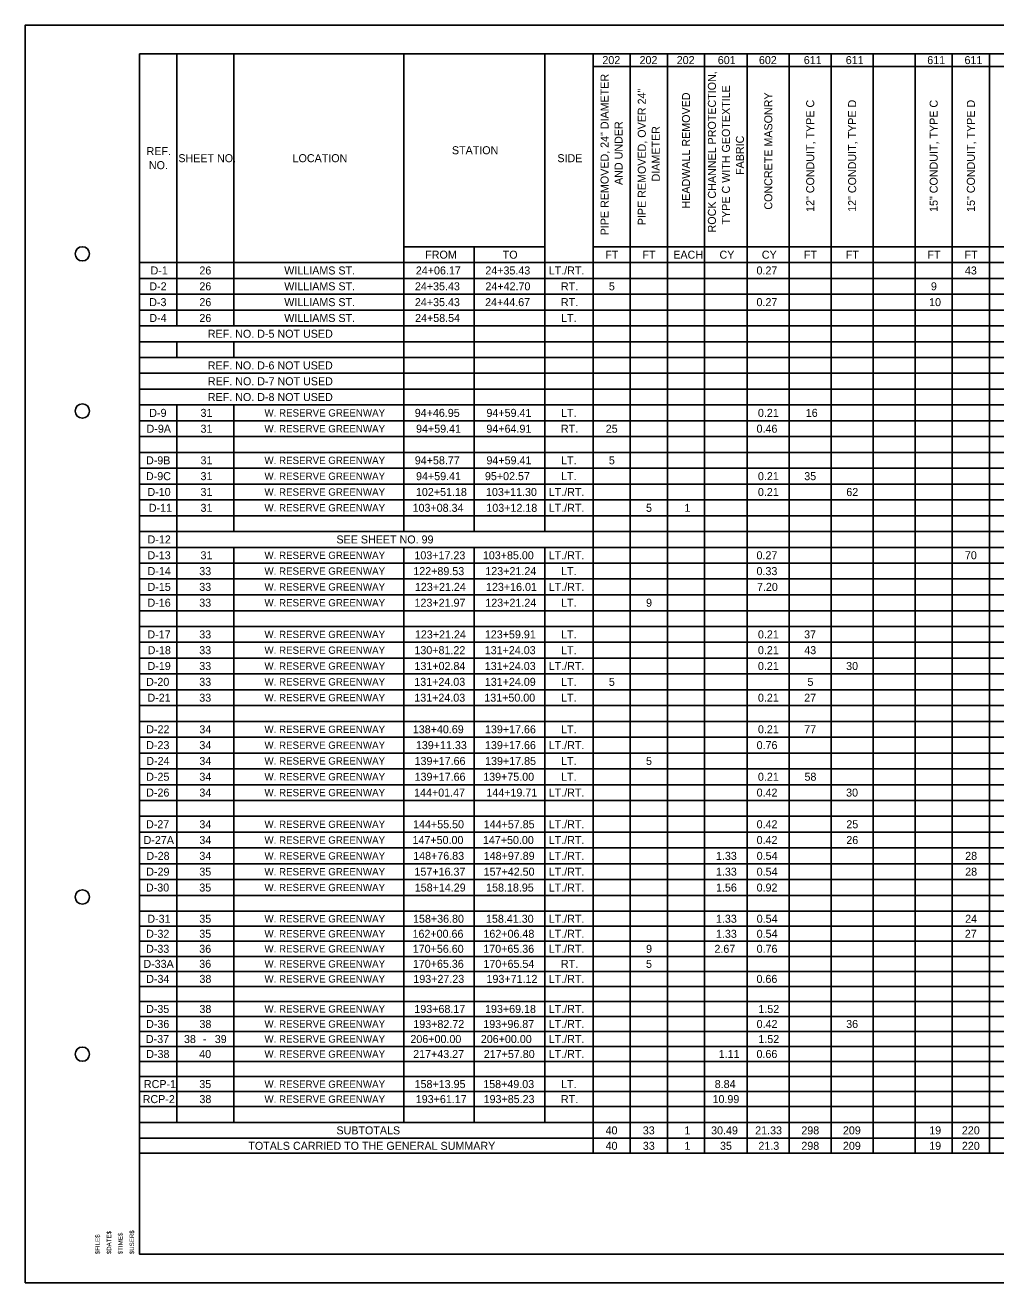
# Model space of a CAD drawing. Extents: x -16 to 102, y -13 to 9.
# Drawn here: x -16.37 to 0.6, y -12.91 to 9.09 of the extents above; entities that cross this region are included whole.
import ezdxf

# ---------------------------------------------------------------- set-up
doc = ezdxf.new("R2010")
doc.units = 0
for name, color, linetype in [('PV_P_EOP', 7, 'Continuous'), ('SH_Border', 7, 'Continuous'), ('SH_Cut_Line', 7, 'Continuous'), ('TX_P_1', 7, 'Continuous'), ('TX_P_Misc', 7, 'Continuous')]:
    doc.layers.add(name, color=color, linetype=linetype)

msp = doc.modelspace()

# ---------------------------------------------------------------- linework, layer by layer
at = {"layer": 'SH_Border'}
msp.add_lwpolyline([(-14.371, 8.593), (17.129, 8.593), (17.129, -12.407), (-14.371, -12.407)], close=True, dxfattribs=at)
for centre in [(-15.371, 5.093), (-15.371, 2.343), (-15.371, -6.157), (-15.371, -8.907)]:
    msp.add_circle(centre, 0.125, dxfattribs=at)
at = {"layer": 'SH_Cut_Line'}
msp.add_lwpolyline([(-16.371, -12.907), (17.629, -12.907), (17.629, 9.093), (-16.371, 9.093)], close=True, dxfattribs=at)
at = {"layer": 'TX_P_1'}
for p, q in [((-14.371, 8.593), (10.564, 8.593)), ((-14.371, 8.593), (-14.371, -10.641)), ((-13.721, 8.593), (-13.721, 3.833)), ((-12.725, 8.593), (-12.725, 3.833)), ((-9.75, 8.593), (-9.75, 0.235)), ((-7.286, 8.593), (-7.286, 0.235)), ((-6.442, 8.593), (-6.442, -10.641)), ((-5.792, 8.593), (-5.792, -10.641)), ((-5.142, 8.593), (-5.142, -10.641)), ((-4.491, 8.593), (-4.491, -10.641)), ((-3.744, 8.593), (-3.744, -10.641)), ((-3.011, 8.593), (-3.011, -10.641)), ((-2.277, 8.593), (-2.277, -10.641)), ((-1.544, 8.593), (-1.544, -10.641)), ((-0.811, 8.593), (-0.811, -10.641)), ((-0.16, 8.593), (-0.16, -10.641)), ((0.49, 8.593), (0.49, -10.641)), ((-6.442, 8.372), (10.564, 8.372)), ((-9.75, 5.217), (-7.286, 5.217)), ((-8.518, 5.217), (-8.518, 0.235)), ((-6.442, 5.217), (10.564, 5.217)), ((-14.371, 4.94), (10.564, 4.94)), ((-14.371, 4.663), (10.564, 4.663)), ((-14.371, 4.386), (10.564, 4.386)), ((-14.371, 4.11), (10.564, 4.11)), ((-14.371, 3.833), (10.564, 3.833)), ((-14.371, 3.556), (10.564, 3.556)), ((-13.721, 3.556), (-13.721, 3.279)), ((-12.725, 3.556), (-12.725, 3.279)), ((-14.371, 3.279), (10.564, 3.279)), ((-14.371, 3.003), (10.564, 3.003)), ((-14.371, 2.726), (10.564, 2.726)), ((-14.371, 2.449), (10.564, 2.449)), ((-13.721, 2.449), (-13.721, -10.101)), ((-12.725, 2.449), (-12.725, 0.235)), ((-14.371, 2.172), (10.564, 2.172)), ((-14.371, 1.896), (10.564, 1.896)), ((-14.371, 1.619), (10.564, 1.619)), ((-14.371, 1.342), (10.564, 1.342)), ((-14.371, 1.065), (10.564, 1.065)), ((-14.371, 0.789), (10.564, 0.789)), ((-14.371, 0.512), (10.564, 0.512)), ((-14.371, 0.235), (10.564, 0.235)), ((-14.371, -0.042), (10.564, -0.042)), ((-12.725, -0.042), (-12.725, -10.101)), ((-9.75, -0.042), (-9.75, -10.101)), ((-8.518, -0.042), (-8.518, -10.101)), ((-7.286, -0.042), (-7.286, -10.101)), ((-14.371, -0.318), (10.564, -0.318)), ((-14.371, -0.595), (10.564, -0.595)), ((-14.371, -0.872), (10.564, -0.872)), ((-14.371, -1.149), (10.564, -1.149)), ((-14.371, -1.425), (10.564, -1.425)), ((-14.371, -1.702), (10.564, -1.702)), ((-14.371, -1.979), (10.564, -1.979)), ((-14.371, -2.256), (10.564, -2.256)), ((-14.371, -2.532), (10.564, -2.532)), ((-14.371, -2.809), (10.564, -2.809)), ((-14.371, -3.086), (10.564, -3.086)), ((-14.371, -3.363), (10.564, -3.363)), ((-14.371, -3.639), (10.564, -3.639)), ((-14.371, -3.916), (10.564, -3.916)), ((-14.371, -4.193), (10.564, -4.193)), ((-14.371, -4.47), (10.564, -4.47)), ((-14.371, -4.746), (10.564, -4.746)), ((-14.371, -5.023), (10.564, -5.023)), ((-14.371, -5.3), (10.564, -5.3)), ((-14.371, -5.577), (10.564, -5.577)), ((-14.371, -5.853), (10.564, -5.853)), ((-14.371, -6.13), (10.564, -6.13)), ((-14.371, -6.407), (10.564, -6.407)), ((-14.371, -6.67), (10.564, -6.67)), ((-14.371, -6.933), (10.564, -6.933)), ((-14.371, -7.196), (10.564, -7.196)), ((-14.371, -7.458), (10.564, -7.458)), ((-14.371, -7.721), (10.564, -7.721)), ((-14.371, -7.984), (10.564, -7.984)), ((-14.371, -8.247), (10.564, -8.247)), ((-14.371, -8.51), (10.564, -8.51)), ((-14.371, -8.773), (10.564, -8.773)), ((-14.371, -9.036), (10.564, -9.036)), ((-14.371, -9.299), (10.564, -9.299)), ((-14.371, -9.562), (10.564, -9.562)), ((-14.371, -9.825), (10.564, -9.825)), ((-14.371, -10.101), (10.564, -10.101)), ((-14.371, -10.378), (10.564, -10.378)), ((-14.371, -10.641), (10.564, -10.641))]:
    msp.add_line(p, q, dxfattribs=at)

# ---------------------------------------------------------------- texts
at = {"layer": 'PV_P_EOP'}
for s, height, p in [('REF.', 0.14, (-14.248, 6.819)), ('SHEET NO.', 0.14, (-13.693, 6.696)), ('LOCATION', 0.14, (-11.695, 6.696)), ('STATION', 0.14, (-8.909, 6.835)), ('SIDE', 0.14, (-7.065, 6.696)), ('NO.', 0.14, (-14.208, 6.574)), ('FROM', 0.14, (-9.376, 5.008)), ('TO', 0.14, (-8.021, 5.008)), ('SUBTOTALS', 0.14, (-10.928, -10.31)), ('TOTALS CARRIED TO THE GENERAL SUMMARY', 0.14004, (-12.469, -10.58))]:
    msp.add_text(s, height=height, dxfattribs=at).set_placement(p)
at = {"layer": 'TX_P_1'}
for s, height, p in [('202', 0.14, (-6.278, 8.412)), ('202', 0.14, (-5.628, 8.412)), ('202', 0.14, (-4.978, 8.412)), ('601', 0.14, (-4.26, 8.412)), ('602', 0.14, (-3.541, 8.412)), ('611', 0.14, (-2.756, 8.412)), ('611', 0.14, (-2.022, 8.412)), ('611', 0.14, (-0.597, 8.412)), ('611', 0.14, (0.054, 8.412)), ('FT', 0.14, (-6.227, 5.008)), ('FT', 0.14, (-5.577, 5.008)), ('EACH', 0.14, (-5.038, 5.008)), ('CY', 0.14, (-4.23, 5.008)), ('CY', 0.14, (-3.49, 5.008)), ('FT', 0.14, (-2.754, 5.008)), ('FT', 0.14, (-2.021, 5.008)), ('FT', 0.14, (-0.595, 5.008)), ('FT', 0.14, (0.055, 5.008)), ('D-1', 0.14, (-14.179, 4.732)), ('26', 0.14, (-13.325, 4.732)), ('WILLIAMS ST.', 0.14004, (-11.841, 4.732)), ('24+06.17', 0.14, (-9.54, 4.732)), ('24+35.43', 0.14, (-8.325, 4.732)), ('LT./RT.', 0.14, (-7.216, 4.732)), ('0.27', 0.14, (-3.583, 4.732)), ('43', 0.14, (0.061, 4.732)), ('D-2', 0.14, (-14.2, 4.455)), ('26', 0.14, (-13.325, 4.455)), ('WILLIAMS ST.', 0.14004, (-11.841, 4.455)), ('24+35.43', 0.14, (-9.556, 4.455)), ('24+42.70', 0.14, (-8.323, 4.455)), ('RT.', 0.14, (-7.003, 4.455)), ('5', 0.14, (-6.165, 4.455)), ('9', 0.14, (-0.533, 4.455)), ('D-3', 0.14, (-14.202, 4.178)), ('26', 0.14, (-13.325, 4.178)), ('WILLIAMS ST.', 0.14004, (-11.841, 4.178)), ('24+35.43', 0.14, (-9.556, 4.178)), ('24+44.67', 0.14, (-8.328, 4.178)), ('RT.', 0.14, (-7.003, 4.178)), ('0.27', 0.14, (-3.583, 4.178)), ('10', 0.14, (-0.565, 4.178)), ('D-4', 0.14, (-14.2, 3.901)), ('26', 0.14, (-13.325, 3.901)), ('WILLIAMS ST.', 0.14004, (-11.841, 3.901)), ('24+58.54', 0.14, (-9.553, 3.901)), ('LT.', 0.14, (-7, 3.901)), ('REF. NO. D-5 NOT USED', 0.14004, (-13.177, 3.625)), ('REF. NO. D-6 NOT USED', 0.14004, (-13.178, 3.071)), ('REF. NO. D-7 NOT USED', 0.14004, (-13.176, 2.794)), ('REF. NO. D-8 NOT USED', 0.14004, (-13.177, 2.518)), ('D-9', 0.14, (-14.201, 2.241)), ('31', 0.14, (-13.305, 2.241)), ('W. RESERVE GREENWAY', 0.12731, (-12.187, 2.247)), ('94+46.95', 0.14, (-9.559, 2.241)), ('94+59.41', 0.14, (-8.305, 2.241)), ('LT.', 0.14, (-7, 2.241)), ('0.21', 0.14, (-3.558, 2.241)), ('16', 0.14, (-2.722, 2.241)), ('D-9A', 0.14, (-14.248, 1.964)), ('31', 0.14, (-13.305, 1.964)), ('W. RESERVE GREENWAY', 0.12731, (-12.187, 1.97)), ('94+59.41', 0.14, (-9.536, 1.964)), ('94+64.91', 0.14, (-8.306, 1.964)), ('RT.', 0.14, (-7.003, 1.964)), ('25', 0.14, (-6.219, 1.964)), ('0.46', 0.14, (-3.582, 1.964)), ('D-9B', 0.14, (-14.258, 1.411)), ('31', 0.14, (-13.305, 1.411)), ('W. RESERVE GREENWAY', 0.12731, (-12.187, 1.417)), ('94+58.77', 0.14, (-9.558, 1.411)), ('94+59.41', 0.14, (-8.305, 1.411)), ('LT.', 0.14, (-7, 1.411)), ('5', 0.14, (-6.165, 1.411)), ('D-9C', 0.14, (-14.259, 1.134)), ('31', 0.14, (-13.305, 1.134)), ('W. RESERVE GREENWAY', 0.12731, (-12.187, 1.14)), ('94+59.41', 0.14, (-9.536, 1.134)), ('95+02.57', 0.14, (-8.332, 1.134)), ('LT.', 0.14, (-7, 1.134)), ('0.21', 0.14, (-3.558, 1.134)), ('35', 0.14, (-2.748, 1.134)), ('D-10', 0.14, (-14.233, 0.857)), ('31', 0.14, (-13.305, 0.857)), ('W. RESERVE GREENWAY', 0.12731, (-12.187, 0.863)), ('102+51.18', 0.14, (-9.538, 0.857)), ('103+11.30', 0.14, (-8.313, 0.857)), ('LT./RT.', 0.14, (-7.216, 0.857)), ('0.21', 0.14, (-3.558, 0.857)), ('62', 0.14, (-2.013, 0.857)), ('D-11', 0.14, (-14.209, 0.58)), ('31', 0.14, (-13.305, 0.58)), ('W. RESERVE GREENWAY', 0.12731, (-12.187, 0.587)), ('103+08.34', 0.14, (-9.597, 0.58)), ('103+12.18', 0.14, (-8.307, 0.58)), ('LT./RT.', 0.14, (-7.216, 0.58)), ('5', 0.14, (-5.515, 0.58)), ('1', 0.14, (-4.843, 0.58)), ('D-12', 0.14, (-14.23, 0.027)), ('SEE SHEET NO. 99', 0.14004, (-10.928, 0.027)), ('D-13', 0.14, (-14.232, -0.25)), ('31', 0.14, (-13.305, -0.25)), ('W. RESERVE GREENWAY', 0.12731, (-12.187, -0.244)), ('103+17.23', 0.14, (-9.565, -0.25)), ('103+85.00', 0.14, (-8.368, -0.25)), ('LT./RT.', 0.14, (-7.216, -0.25)), ('0.27', 0.14, (-3.583, -0.25)), ('70', 0.14, (0.061, -0.25)), ('D-14', 0.14, (-14.23, -0.527)), ('33', 0.14, (-13.327, -0.527)), ('W. RESERVE GREENWAY', 0.12731, (-12.187, -0.52)), ('122+89.53', 0.14, (-9.584, -0.527)), ('123+21.24', 0.14, (-8.325, -0.527)), ('LT.', 0.14, (-7, -0.527)), ('0.33', 0.14, (-3.583, -0.527)), ('LT./RT.', 0.14, (-7.216, -0.803)), ('D-15', 0.14, (-14.231, -0.803)), ('33', 0.14, (-13.327, -0.803)), ('W. RESERVE GREENWAY', 0.12731, (-12.187, -0.797)), ('123+21.24', 0.14, (-9.556, -0.803)), ('123+16.01', 0.14, (-8.313, -0.803)), ('7.20', 0.14, (-3.575, -0.803)), ('D-16', 0.14, (-14.232, -1.08)), ('33', 0.14, (-13.327, -1.08)), ('W. RESERVE GREENWAY', 0.12731, (-12.187, -1.074)), ('123+21.97', 0.14, (-9.563, -1.08)), ('123+21.24', 0.14, (-8.325, -1.08)), ('LT.', 0.14, (-7, -1.08)), ('9', 0.14, (-5.514, -1.08)), ('D-17', 0.14, (-14.234, -1.634)), ('33', 0.14, (-13.327, -1.634)), ('W. RESERVE GREENWAY', 0.12731, (-12.187, -1.627)), ('123+21.24', 0.14, (-9.556, -1.634)), ('123+59.91', 0.14, (-8.333, -1.634)), ('LT.', 0.14, (-7, -1.634)), ('0.21', 0.14, (-3.558, -1.634)), ('37', 0.14, (-2.751, -1.634)), ('D-18', 0.14, (-14.229, -1.91)), ('33', 0.14, (-13.327, -1.91)), ('W. RESERVE GREENWAY', 0.12731, (-12.187, -1.904)), ('130+81.22', 0.14, (-9.565, -1.91)), ('131+24.03', 0.14, (-8.335, -1.91)), ('LT.', 0.14, (-7, -1.91)), ('0.21', 0.14, (-3.558, -1.91)), ('43', 0.14, (-2.748, -1.91)), ('D-19', 0.14, (-14.231, -2.187)), ('33', 0.14, (-13.327, -2.187)), ('W. RESERVE GREENWAY', 0.12731, (-12.187, -2.181)), ('131+02.84', 0.14, (-9.564, -2.187)), ('131+24.03', 0.14, (-8.335, -2.187)), ('LT./RT.', 0.14, (-7.216, -2.187)), ('0.21', 0.14, (-3.558, -2.187)), ('30', 0.14, (-2.016, -2.187)), ('D-20', 0.14, (-14.257, -2.464)), ('33', 0.14, (-13.327, -2.464)), ('W. RESERVE GREENWAY', 0.12731, (-12.187, -2.458)), ('131+24.03', 0.14, (-9.567, -2.464)), ('131+24.09', 0.14, (-8.334, -2.464)), ('LT.', 0.14, (-7, -2.464)), ('5', 0.14, (-6.165, -2.464)), ('5', 0.14, (-2.692, -2.464)), ('D-21', 0.14, (-14.233, -2.741)), ('33', 0.14, (-13.327, -2.741)), ('W. RESERVE GREENWAY', 0.12731, (-12.187, -2.734)), ('131+24.03', 0.14, (-9.567, -2.741)), ('131+50.00', 0.14, (-8.343, -2.741)), ('LT.', 0.14, (-7, -2.741)), ('0.21', 0.14, (-3.558, -2.741)), ('27', 0.14, (-2.749, -2.741)), ('D-22', 0.14, (-14.254, -3.294)), ('34', 0.14, (-13.325, -3.294)), ('W. RESERVE GREENWAY', 0.12731, (-12.187, -3.288)), ('138+40.69', 0.14, (-9.593, -3.294)), ('139+17.66', 0.14, (-8.331, -3.294)), ('LT.', 0.14, (-7, -3.294)), ('0.21', 0.14, (-3.558, -3.294)), ('77', 0.14, (-2.749, -3.294)), ('D-23', 0.14, (-14.255, -3.571)), ('34', 0.14, (-13.325, -3.571)), ('W. RESERVE GREENWAY', 0.12731, (-12.187, -3.565)), ('139+11.33', 0.14, (-9.539, -3.571)), ('139+17.66', 0.14, (-8.331, -3.571)), ('LT./RT.', 0.14, (-7.216, -3.571)), ('0.76', 0.14, (-3.581, -3.571)), ('D-24', 0.14, (-14.253, -3.848)), ('34', 0.14, (-13.325, -3.848)), ('W. RESERVE GREENWAY', 0.12731, (-12.187, -3.841)), ('139+17.66', 0.14, (-9.562, -3.848)), ('139+17.85', 0.14, (-8.329, -3.848)), ('LT.', 0.14, (-7, -3.848)), ('5', 0.14, (-5.515, -3.848)), ('D-25', 0.14, (-14.255, -4.124)), ('34', 0.14, (-13.325, -4.124)), ('W. RESERVE GREENWAY', 0.12731, (-12.187, -4.118)), ('139+17.66', 0.14, (-9.562, -4.124)), ('139+75.00', 0.14, (-8.362, -4.124)), ('LT.', 0.14, (-7, -4.124)), ('0.21', 0.14, (-3.558, -4.124)), ('58', 0.14, (-2.744, -4.124)), ('D-26', 0.14, (-14.255, -4.401)), ('34', 0.14, (-13.325, -4.401)), ('W. RESERVE GREENWAY', 0.12731, (-12.187, -4.395)), ('144+01.47', 0.14, (-9.57, -4.401)), ('144+19.71', 0.14, (-8.307, -4.401)), ('LT./RT.', 0.14, (-7.216, -4.401)), ('0.42', 0.14, (-3.581, -4.401)), ('30', 0.14, (-2.016, -4.401)), ('D-27', 0.14, (-14.258, -4.955)), ('34', 0.14, (-13.325, -4.955)), ('W. RESERVE GREENWAY', 0.12731, (-12.187, -4.948)), ('144+55.50', 0.14, (-9.588, -4.955)), ('144+57.85', 0.14, (-8.353, -4.955)), ('LT./RT.', 0.14, (-7.216, -4.955)), ('0.42', 0.14, (-3.581, -4.955)), ('25', 0.14, (-2.012, -4.955)), ('D-27A', 0.14, (-14.3, -5.231)), ('34', 0.14, (-13.325, -5.231)), ('W. RESERVE GREENWAY', 0.12731, (-12.187, -5.225)), ('147+50.00', 0.14, (-9.598, -5.231)), ('147+50.00', 0.14, (-8.367, -5.231)), ('LT./RT.', 0.14, (-7.216, -5.231)), ('0.42', 0.14, (-3.581, -5.231)), ('26', 0.14, (-2.013, -5.231)), ('D-28', 0.14, (-14.252, -5.508)), ('34', 0.14, (-13.325, -5.508)), ('W. RESERVE GREENWAY', 0.12731, (-12.187, -5.502)), ('148+76.83', 0.14, (-9.586, -5.508)), ('148+97.89', 0.14, (-8.353, -5.508)), ('LT./RT.', 0.14, (-7.216, -5.508)), ('1.33', 0.14, (-4.292, -5.508)), ('0.54', 0.14, (-3.58, -5.508)), ('28', 0.14, (0.066, -5.508)), ('D-29', 0.14, (-14.254, -5.785)), ('35', 0.14, (-13.326, -5.785)), ('W. RESERVE GREENWAY', 0.12731, (-12.187, -5.779)), ('157+16.37', 0.14, (-9.564, -5.785)), ('157+42.50', 0.14, (-8.354, -5.785)), ('LT./RT.', 0.14, (-7.216, -5.785)), ('1.33', 0.14, (-4.292, -5.785)), ('0.54', 0.14, (-3.58, -5.785)), ('28', 0.14, (0.066, -5.785)), ('D-30', 0.14, (-14.259, -6.062)), ('35', 0.14, (-13.326, -6.062)), ('W. RESERVE GREENWAY', 0.12731, (-12.187, -6.055)), ('158+14.29', 0.14, (-9.559, -6.062)), ('158.18.95', 0.14, (-8.311, -6.062)), ('LT./RT.', 0.14, (-7.216, -6.062)), ('1.56', 0.14, (-4.291, -6.062)), ('0.92', 0.14, (-3.581, -6.062)), ('D-31', 0.14, (-14.235, -6.608)), ('35', 0.14, (-13.326, -6.608)), ('W. RESERVE GREENWAY', 0.12731, (-12.187, -6.602)), ('158+36.80', 0.14, (-9.589, -6.608)), ('158.41.30', 0.14, (-8.313, -6.608)), ('LT./RT.', 0.14, (-7.216, -6.608)), ('1.33', 0.14, (-4.292, -6.608)), ('0.54', 0.14, (-3.58, -6.608)), ('24', 0.14, (0.065, -6.608)), ('D-32', 0.14, (-14.256, -6.871)), ('35', 0.14, (-13.326, -6.871)), ('W. RESERVE GREENWAY', 0.12731, (-12.187, -6.865)), ('162+00.66', 0.14, (-9.598, -6.871)), ('162+06.48', 0.14, (-8.358, -6.871)), ('LT./RT.', 0.14, (-7.216, -6.871)), ('1.33', 0.14, (-4.292, -6.871)), ('0.54', 0.14, (-3.58, -6.871)), ('27', 0.14, (0.06, -6.871)), ('D-33', 0.14, (-14.257, -7.134)), ('36', 0.14, (-13.327, -7.134)), ('W. RESERVE GREENWAY', 0.12731, (-12.187, -7.128)), ('170+56.60', 0.14, (-9.594, -7.134)), ('170+65.36', 0.14, (-8.361, -7.134)), ('LT./RT.', 0.14, (-7.216, -7.134)), ('9', 0.14, (-5.514, -7.134)), ('2.67', 0.14, (-4.319, -7.134)), ('0.76', 0.14, (-3.581, -7.134)), ('D-33A', 0.14, (-14.304, -7.397)), ('36', 0.14, (-13.327, -7.397)), ('170+65.36', 0.14, (-9.592, -7.397)), ('170+65.54', 0.14, (-8.358, -7.397)), ('RT.', 0.14, (-7.003, -7.397)), ('5', 0.14, (-5.515, -7.397)), ('W. RESERVE GREENWAY', 0.12731, (-12.187, -7.391)), ('D-34', 0.14, (-14.255, -7.66)), ('38', 0.14, (-13.324, -7.66)), ('W. RESERVE GREENWAY', 0.12731, (-12.187, -7.654)), ('193+27.23', 0.14, (-9.584, -7.66)), ('193+71.12', 0.14, (-8.304, -7.66)), ('LT./RT.', 0.14, (-7.216, -7.66)), ('0.66', 0.14, (-3.583, -7.66)), ('D-35', 0.14, (-14.257, -8.186)), ('38', 0.14, (-13.324, -8.186)), ('W. RESERVE GREENWAY', 0.12731, (-12.187, -8.179)), ('193+68.17', 0.14, (-9.566, -8.186)), ('193+69.18', 0.14, (-8.33, -8.186)), ('LT./RT.', 0.14, (-7.216, -8.186)), ('1.52', 0.14, (-3.55, -8.186)), ('D-36', 0.14, (-14.257, -8.449)), ('38', 0.14, (-13.324, -8.449)), ('W. RESERVE GREENWAY', 0.12731, (-12.187, -8.442)), ('193+82.72', 0.14, (-9.584, -8.449)), ('193+96.87', 0.14, (-8.36, -8.449)), ('LT./RT.', 0.14, (-7.216, -8.449)), ('0.42', 0.14, (-3.581, -8.449)), ('36', 0.14, (-2.015, -8.449)), ('D-37', 0.14, (-14.26, -8.712)), ('38', 0.14, (-13.594, -8.712)), ('39', 0.14, (-13.056, -8.712)), ('W. RESERVE GREENWAY', 0.12731, (-12.187, -8.705)), ('206+00.00', 0.14, (-9.635, -8.712)), ('206+00.00', 0.14, (-8.404, -8.712)), ('LT./RT.', 0.14, (-7.216, -8.712)), ('1.52', 0.14, (-3.55, -8.712)), ('-', 0.14, (-13.262, -8.712)), ('D-38', 0.14, (-14.254, -8.974)), ('40', 0.14, (-13.328, -8.974)), ('W. RESERVE GREENWAY', 0.12731, (-12.187, -8.968)), ('217+43.27', 0.14, (-9.586, -8.974)), ('217+57.80', 0.14, (-8.352, -8.974)), ('LT./RT.', 0.14, (-7.216, -8.974)), ('1.11', 0.14, (-4.244, -8.974)), ('0.66', 0.14, (-3.583, -8.974)), ('RCP-1', 0.14, (-14.295, -9.5)), ('35', 0.14, (-13.326, -9.5)), ('W. RESERVE GREENWAY', 0.12731, (-12.187, -9.494)), ('158+13.95', 0.14, (-9.562, -9.5)), ('158+49.03', 0.14, (-8.361, -9.5)), ('LT.', 0.14, (-7, -9.5)), ('8.84', 0.14, (-4.314, -9.5)), ('RCP-2', 0.14, (-14.316, -9.763)), ('38', 0.14, (-13.324, -9.763)), ('W. RESERVE GREENWAY', 0.12731, (-12.187, -9.757)), ('193+61.17', 0.14, (-9.541, -9.763)), ('193+85.23', 0.14, (-8.355, -9.763)), ('RT.', 0.14, (-7.003, -9.763)), ('10.99', 0.14, (-4.352, -9.763)), ('40', 0.14, (-6.222, -10.31)), ('33', 0.14, (-5.571, -10.31)), ('1', 0.14, (-4.843, -10.31)), ('30.49', 0.14, (-4.377, -10.31)), ('21.33', 0.14, (-3.606, -10.31)), ('298', 0.14, (-2.799, -10.31)), ('209', 0.14, (-2.072, -10.31)), ('19', 0.14, (-0.563, -10.31)), ('220', 0.14, (0.008, -10.31)), ('40', 0.14, (-6.222, -10.58)), ('33', 0.14, (-5.571, -10.58)), ('1', 0.14, (-4.843, -10.58)), ('35', 0.14, (-4.221, -10.58)), ('21.3', 0.14, (-3.55, -10.58)), ('298', 0.14, (-2.799, -10.58)), ('209', 0.14, (-2.072, -10.58)), ('19', 0.14, (-0.563, -10.58)), ('220', 0.14, (0.008, -10.58))]:
    msp.add_text(s, height=height, dxfattribs=at).set_placement(p)
for s, height, p in [('PIPE REMOVED, 24" DIAMETER', 0.14004, (-6.17, 5.417)), ('ROCK CHANNEL PROTECTION,', 0.14004, (-4.293, 5.467)), ('PIPE REMOVED, OVER 24"', 0.14004, (-5.519, 5.594)), ('TYPE C WITH GEOTEXTILE', 0.14004, (-4.048, 5.607)), ('HEADWALL REMOVED', 0.14004, (-4.746, 5.886)), ('CONCRETE MASONRY', 0.14004, (-3.307, 5.866)), ('12" CONDUIT, TYPE C', 0.14004, (-2.574, 5.827)), ('12" CONDUIT, TYPE D', 0.14004, (-1.841, 5.828)), ('15" CONDUIT, TYPE C', 0.14004, (-0.415, 5.826)), ('15" CONDUIT, TYPE D', 0.14004, (0.235, 5.827)), ('AND UNDER', 0.14, (-5.925, 6.298)), ('DIAMETER', 0.14, (-5.274, 6.36)), ('FABRIC', 0.14, (-3.803, 6.473))]:
    msp.add_text(s, height=height, rotation=90, dxfattribs=at).set_placement(p)
at = {"layer": 'TX_P_Misc'}
for s, p in [('$FILE$', (-15.067, -12.407)), ('$DATE$', (-14.867, -12.407)), ('$TIME$', (-14.667, -12.407)), ('$USER$', (-14.467, -12.407))]:
    msp.add_text(s, height=0.078, rotation=90, dxfattribs=at).set_placement(p)

doc.saveas('drawing.dxf')
